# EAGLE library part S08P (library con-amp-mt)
AMP MT CONNECTOR
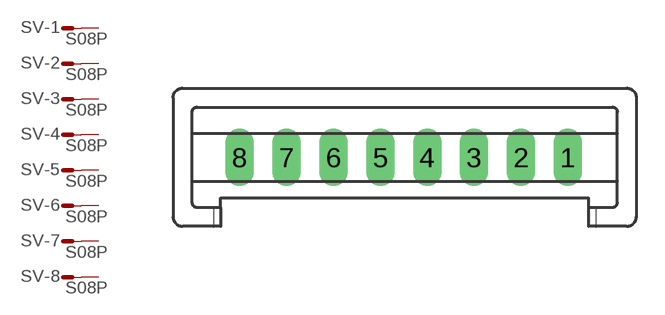
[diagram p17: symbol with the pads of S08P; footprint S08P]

Designator prefix SV; gates -1=M -2=M -3=M -4=M -5=M -6=M -7=M -8=M

## S08P (OC_FARNELL: unknown; OC_NEWARK: unknown)  [S08P]
1  -1:S  pas
2  -2:S  pas
3  -3:S  pas
4  -4:S  pas
5  -5:S  pas
6  -6:S  pas
7  -7:S  pas
8  -8:S  pas

## Footprint S08P (pad centres in mm)
AMP MT CONNECTOR
drill 1.016 long: 1 8.75,0; 2 6.25,0; 3 3.75,0; 4 1.25,0; 5 -1.25,0; 6 -3.75,0; 7 -6.25,0; 8 -8.75,0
